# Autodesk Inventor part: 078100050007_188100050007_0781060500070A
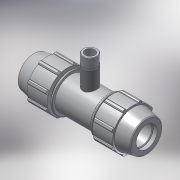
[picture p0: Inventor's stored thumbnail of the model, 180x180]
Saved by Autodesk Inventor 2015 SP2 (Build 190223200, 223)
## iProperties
Created: 2017-02
Part Number: 078100050007_188100050007_0781060500070A
Material: PVC-Piping
Description: PLASSON COUPLER WITH RISER 50-3/4"
Document SubType Name: Modeling
Designer: KIM
Mass: 92.6774 g
Surface Area: 199.44 cm^2
Volume: 66.1981 cm^3
Density: 1.4 g/cm^3
Appearance: Smooth - White
Author: Кирилл
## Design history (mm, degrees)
derived "07810.ipt"
feature "Solid1::07810.ipt"
feature "Solid2::07810.ipt"
tag "TaggingFeature1"
body "Solid1"
other parameters: "d4" = 10.16667, "d5" = 29.28, "d7" = 96, "d11" = 4.06667, "d13" = 120 deg, "d15" = 12 deg, "d16" = 83.52, "d18" = 2.5, "d19" = 35 deg, "d20" = 17.5 deg, "d21" = 89.28, "d23" = 0, "d25" = 360 deg, "d27" = 1.92, "d33" = 1, "d42" = 43.92, "d43" = 2.88, "d46" = 1.5, "d68" = 4.06667, "d73" = 26.441, "d74" = 18, "d76" = 18.5087, "d77" = 21.6, "d80" = 0.79323, "d91" = 72, "d93" = 98, "d95" = 45, "d99" = 244, "d101" = 0, "d103" = 0, "d105" = 0, "d106" = 26.96982, "E_" = 96, "l_" = 98, "l_2" = 18, "H_" = 244, "R_" = 26.441
